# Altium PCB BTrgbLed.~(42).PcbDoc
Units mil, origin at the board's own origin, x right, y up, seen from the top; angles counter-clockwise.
Board outline 3886.28 x 3884.79 mil, 2 copper layers (Top Layer, Bottom Layer); 13 components, 12 nets, 62 pads, 7 vias.
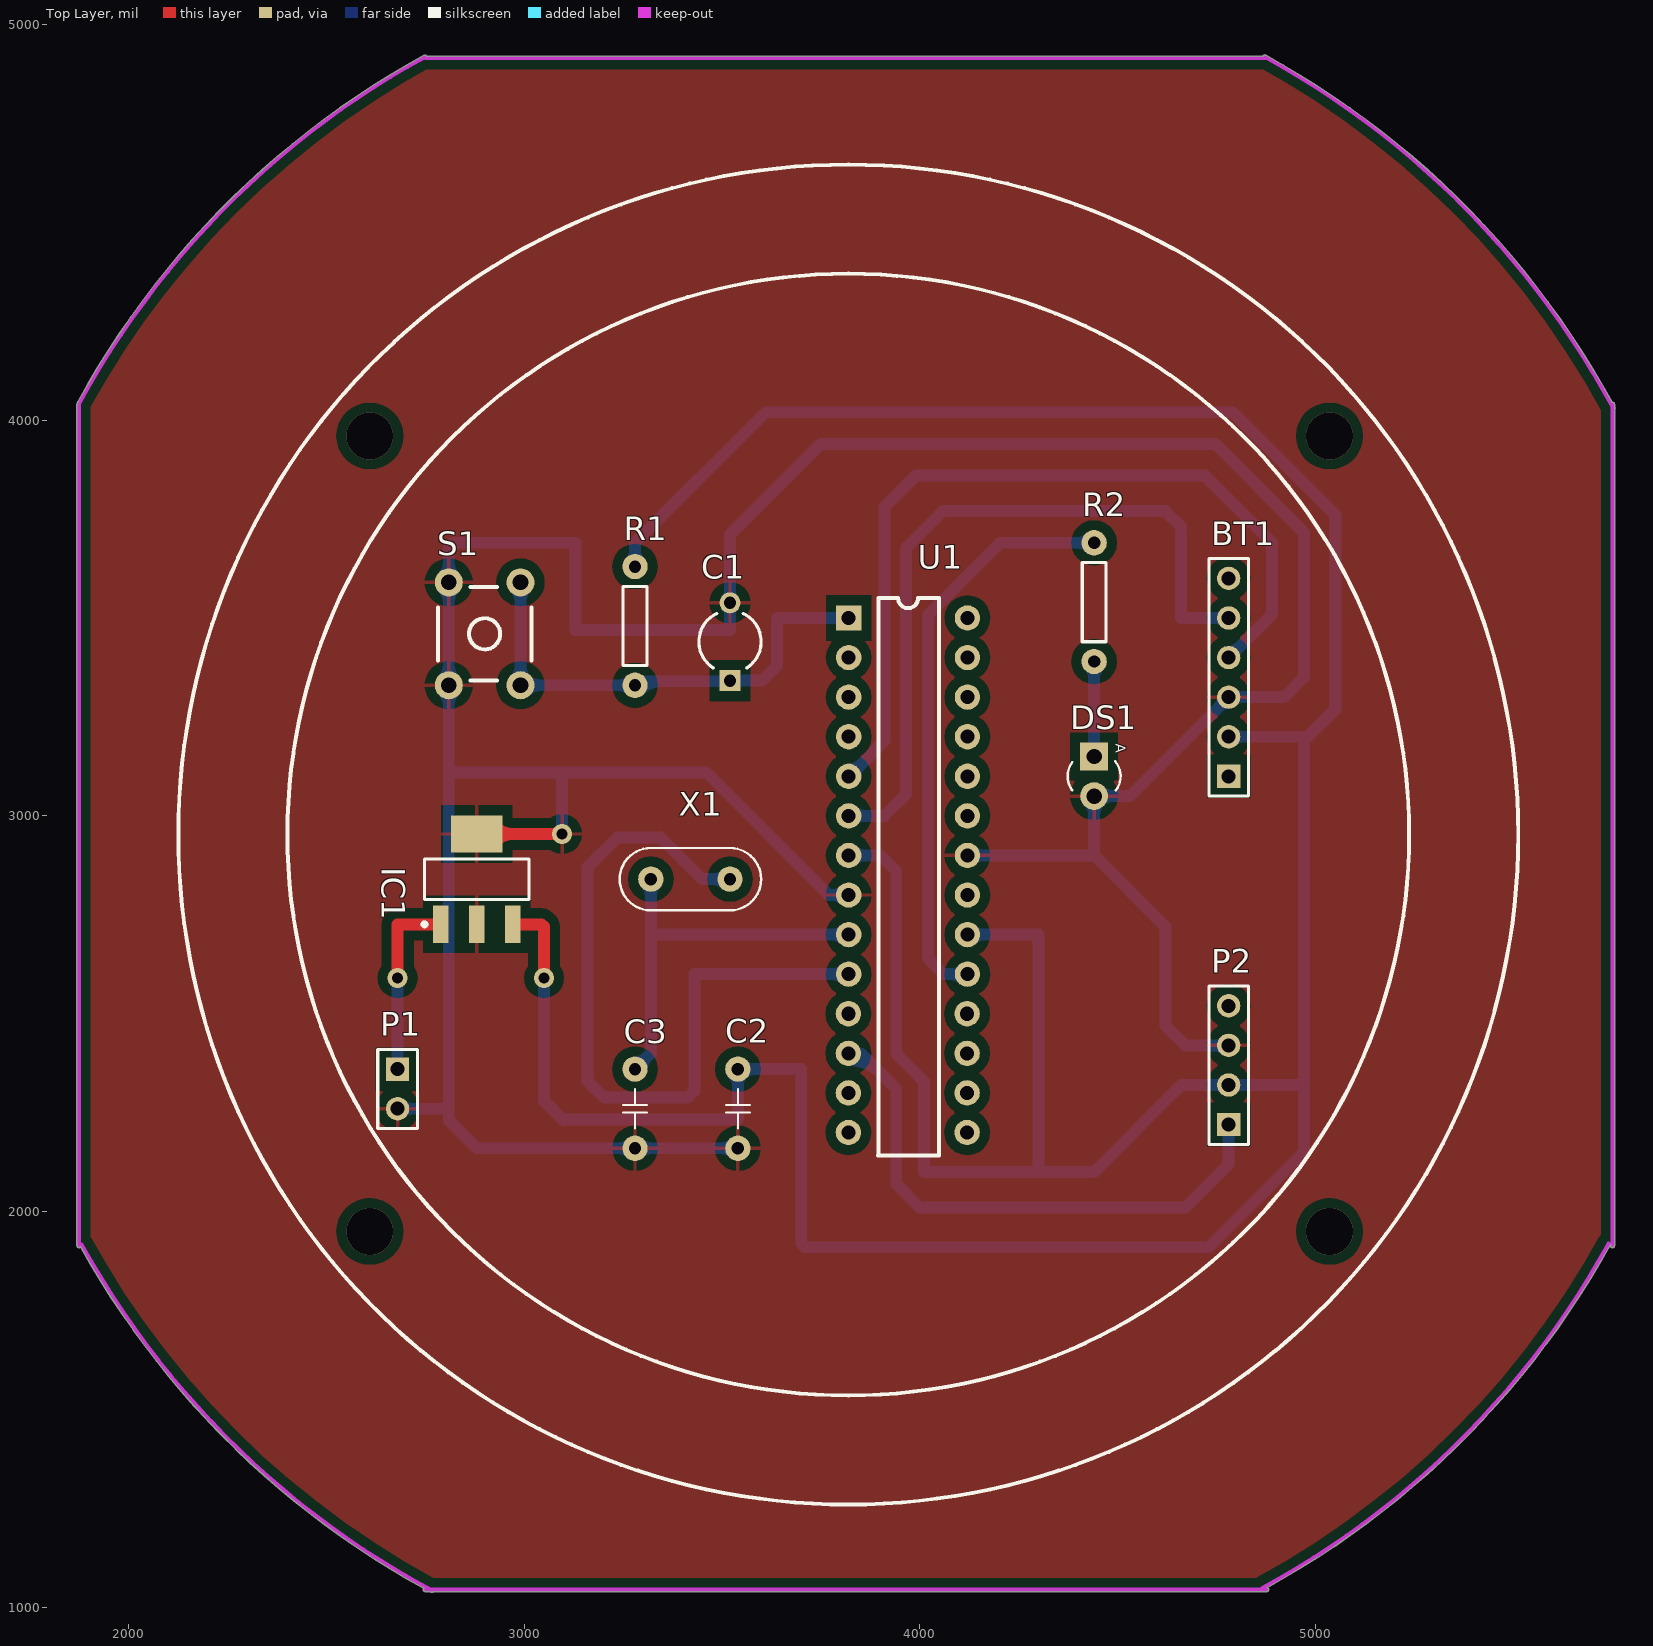
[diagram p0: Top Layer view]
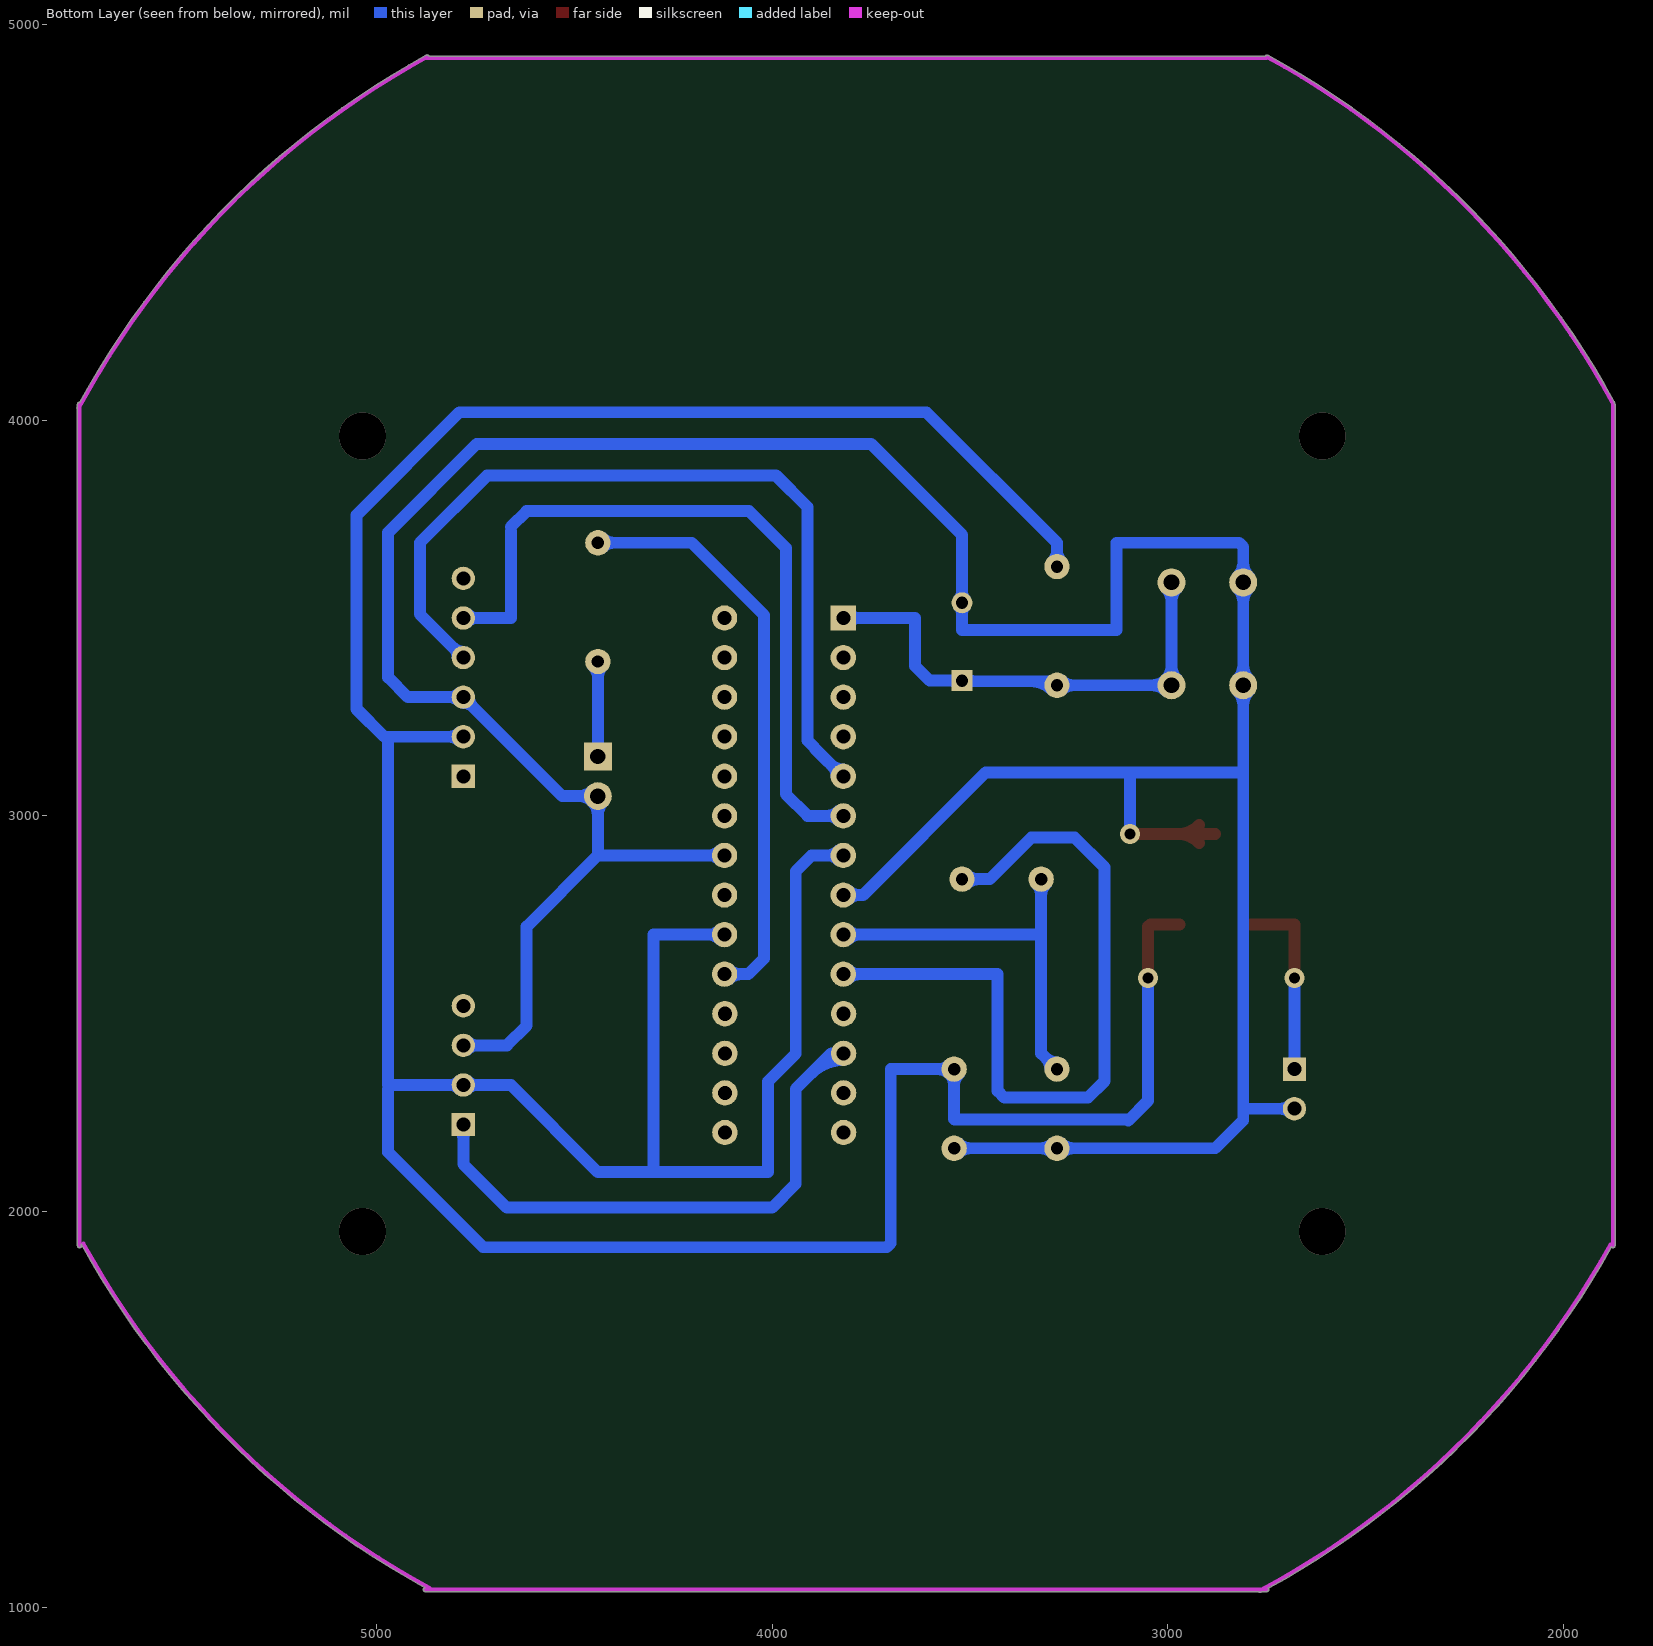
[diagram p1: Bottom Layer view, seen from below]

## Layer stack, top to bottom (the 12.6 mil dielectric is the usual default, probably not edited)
Top Layer: signal copper 1.4
Dielectric: dielectric 12.6, FR-4, Dk 4.8
Bottom Layer: signal copper 1.4

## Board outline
2750,1039.98 2761.53,1039.98 ccw(c3810.28,2985) 2764.5,1038.38 ccw(c2766.88,1042.8) 2771.03,1039.98 4875.98,1039.98 ccw(c4875.98,1045) 4881,1045 ccw(c4875.98,1045) 4877.16,1049.88 ccw(c3810.28,2985) 5744.74,1916.92 ccw(c5740.35,1919.34) 5744.98,1917.43 5744.98,1914.02 ccw(c5750,1914.02) 5755.02,1914.02 5755.02,4027.36 ccw(c5751.25,4030.67) 5756.26,4030.67 ccw(c5751.25,4030.67) 5755.66,4033.05 ccw(c3810.28,2985) 5755.02,4034.26 5755.02,4040 ccw(c5750,4040) 5749.21,4044.95 ccw(c3810.28,2985) 4873.82,4921.96 ccw(c4871.41,4917.56) 4867.03,4920.02 2752.96,4920.02 ccw(c2748.72,4917.33) 2746.3,4921.73 ccw(c3810.28,2985) 1872.41,4046.9 ccw(c1876.81,4044.49) 1871.83,4043.89 ccw(c1875,4040) 1869.98,4040 1869.98,1914.02 ccw(c1875,1914.02) 1879.06,1911.07 ccw(c3810.28,2985) 2746.23,1048.31 ccw(c2750,1045)

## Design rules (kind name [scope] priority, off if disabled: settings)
Clearance 舖銅安全間距 [All] p1: gap=25
Clearance [All] p2: gap=10
PolygonConnect [All] p1: connectstyle=Relief reliefconductorwidth=10 reliefentries=4 polygonreliefangle="90 Angle"
RoutingLayers [All] p1: top layer_v5=FALSE bottom layer_v5=TRUE
RoutingVias [All] p1: holewidth=28 width=50 viastyle="Through Hole" minholewidth=28 minwidth=50 maxholewidth=28 maxwidth=50
SilkscreenOverComponentPads [All] p1: minsilkscreentomaskgap=10
SolderMaskExpansion [All] p1: expansion=4
Width [All] p1: maxlimit=40 minlimit=20 preferedwidth=30
26 further rules are at their usual default settings.

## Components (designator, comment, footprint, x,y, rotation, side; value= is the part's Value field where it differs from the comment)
BT1 "Bluetooth" Bluetooth 4780,3100 r90 top
C1 "47uF" CAPR5-4X5 3520,3440 r90 top
C2 "22pF" C200 3540,2260 r0 top
C3 "22pF" C200 3280,2260 r180 top
DS1 "TX-LED" LED-3mm_G 4440,3100 r270 top
IC1 "AM1117-5V" SOT-223 2880,2840 r90 top
P1 "12V" HDR1X2 2680,2360 r270 top
P2 "環形LED燈" HDR1X4 4780,2220 r90 top
R1 "10k" AXIAL-0.3 3280,3480 r270 top
R2 "220" AXIAL-0.3 4440,3540 r90 top
S1 "SW-PB" TACK6 2900,3460 r90 top
U1 "ATmega328" DIP-28 3820,3500 r270 top
X1 "16MHz" XTAL4-8 3420,2840 r0 top

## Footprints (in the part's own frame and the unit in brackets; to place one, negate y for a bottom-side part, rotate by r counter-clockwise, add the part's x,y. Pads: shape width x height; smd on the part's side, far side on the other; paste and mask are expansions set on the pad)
AXIAL-0.3 [mil] "0.3\" Resistor; 2 Leads"
  round 64 hole 31.5: 1(-150,0) 2(150,0)
  silkscreen extent -100,-30 100,30, body extent -161,-39 165,39, height 86
Bluetooth [mm]
  rect 1.5x1.5 hole 0.9: 1(0,0)
  round 1.5 hole 0.9: 2(2.54,0) 3(5.08,0) 4(7.62,0) 5(10.16,0) 6(12.7,0)
  silkscreen extent -1.27,-1.27 13.97,1.27, body extent -1.25,-1.3 13.97,1.28, height 11
C200 [mil] "塑膠電容器"
  round 64 hole 31.5: 1(0,100) 2(0,-100)
  silkscreen extent -30,-50 30,50, body extent -41,-136 39,135, height 354
CAPR5-4X5 [mm] "Capacitor; 2 Leads"
  rect 1.35x1.35 hole 0.8: 1(-2.5,0)
  round 1.35 hole 0.8: 2(2.5,0)
  silkscreen extent -1.69,-2 1.82,2
DIP-28 [mil]
  rect 64x64 hole 35.43: 1(0,0)
  round 64 hole 35.43: 2(100,0) 3(200,0) 4(300,0) 5(400,0) 6(500,0) 7(600,0) 8(700,0) 9(800,0) 10(900,0) 11(1000,-0.79) 12(1100,-0.79) 13(1200,-0.79) 14(1300,-0.79) 15(1300,299.21) 16(1200,299.21) 17(1100,299.21) 18(1000,299.21) 19(900,300) 20(800,300) 21(700,300) 22(600,300) 23(500,300) 24(400,300) 25(300,300) 26(200,300) 27(100,300) 28(0,300)
  silkscreen extent -50,74 1358,228, body extent -53,-5 1358,304, height 209
HDR1X2 [mm] "Connector; Header; 2 Position"
  rect 1.5x1.5 hole 0.9: 1(0,0)
  round 1.5 hole 0.9: 2(2.54,0)
  silkscreen extent -1.27,-1.27 3.81,1.27
HDR1X4 [mm] "Connector; Header; 4 Position"
  rect 1.5x1.5 hole 0.9: 1(0,0)
  round 1.5 hole 0.9: 2(2.54,0) 3(5.08,0) 4(7.62,0)
  silkscreen extent -1.27,-1.27 8.89,1.27
LED-3mm_G [mil] "3mm LED_Green"
  rect 70x70 hole 39: 1(-50,0)
  round 70 hole 39: 2(50,0)
  silkscreen extent -38,-67 35,67, body extent -66,-68 67,66, height 181
SOT-223 [mm] "SOT223, 4-Leads, Body 6.7x7.3mm (max), Pitch 2.30mm, IPC Medium Density"
  rect 2.4x1 smd: 1(-2.9,2.3) 2(-2.9,0) 3(-2.9,-2.3)
  rect 2.4x3.3 smd: 2(2.9,0)
  silkscreen extent -3.02,-3.35 1.3,3.47, body extent -1.86,-3.35 1.86,3.35, height 1.8
TACK6 [mm]
  round 1.8 hole 1: 1(-3.3,2.3) 1(3.3,2.3) 2(-3.3,-2.3) 2(3.3,-2.3)
  silkscreen extent -3,-3 3,3, body extent -3,-3.01 3.08,3.04, height 8
XTAL4-8 [mil]
  round 64 hole 31.5: 1(-100,0) 2(100,0)
  silkscreen extent -179,-79 179,79, body extent -178,-80 192,79, height 157

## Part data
C1: library part "Cap Pol1", "Polarized Capacitor (Radial)"
C2 C3: library part Cap, "Capacitor"
DS1: library part LED, "Typical INFRARED GaAs LED"
IC1: library part AM1117
P1: library part "Header 2", "Header, 2-Pin"
P2: library part "Header 4", "Header, 4-Pin"
R1 R2: library part Res, "Resistor"
S1: "Switch"
U1: "Arduino"
X1: library part XTAL, "Crystal Oscillator"

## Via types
v1: diameter 118.11, hole 118.11, Top Layer to Bottom Layer, 4 vias
v2: diameter 50, hole 28, Top Layer to Bottom Layer, 3 vias

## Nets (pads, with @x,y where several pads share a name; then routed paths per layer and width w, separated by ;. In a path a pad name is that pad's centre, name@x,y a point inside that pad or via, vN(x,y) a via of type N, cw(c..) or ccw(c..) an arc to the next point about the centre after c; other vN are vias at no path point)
DI: P2.1 U1.12 | length 1699.9
  Bottom Layer w30: U1.12 3850,2400 3940,2310 3940,2070 4000,2010 4670,2010 4780,2120 P2.1 ; 4780,2184.93 cw(c4815.07,2184.93) 4790.27,2209.73 ccw(c4815.07,2184.93) 4780,2184.93 ; 4780,2184.93 ccw(c4744.93,2184.93) 4769.73,2209.73 cw(c4744.93,2184.93) 4780,2184.93 ; U1.12@3819.21,2383 cw(c3819.21,2267.63) 3900.79,2349.21 ccw(c3819.21,2267.63) U1.12@3819.21,2383
DO: P2.4
GND: BT1.3 C1.2 C2.2 C3.1 DS1.2 IC1.2 P1.2 P2.3 S1.1 U1.8 U1.22 | length 11241.6
  Top Layer w30: IC1.2@2880,2954.17 v2(3095.83,2954.17) ; 2975.56,2954.17 cw(c2975.56,3032.02) 2920.52,2976.97 ccw(c2975.56,3032.02) 2975.56,2954.17 ; 2975.56,2954.17 ccw(c2975.56,2876.33) 2920.52,2931.37 cw(c2975.56,2876.33) 2975.56,2954.17
  Bottom Layer w30: P1.2 2804.45,2260 ; S1.1@2809.45,3580.49 2809.45,3330.08 2809.45,2230.55 2880,2160 C3.1 C2.2 ; S1.1@2809.45,3589.92 2809.45,3679.45 2820,3690 3130,3690 3130,3470 3520,3470 C1.2 3520,3710 3750,3940 4746,3940 4970,3716 4970,3350 4920,3300 BT1.3 4530,3050 DS1.2 4440,2900 ; 2819.45,3110 3095.83,3110 ; v2(3095.83,2954.17) 3095.83,3110 ; U1.8 3770,2800 3460,3110 3095.83,3110 ; U1.22 4440,2900 ; P2.3 4670,2420 4620,2470 4620,2720 4440,2900 ; 2715.07,2260 cw(c2715.07,2295.07) 2690.27,2270.27 ccw(c2715.07,2295.07) 2715.07,2260 ; 2715.07,2260 ccw(c2715.07,2224.93) 2690.27,2249.73 cw(c2715.07,2224.93) 2715.07,2260 ; 2809.45,3280.75 cw(c2858.78,3280.75) 2823.9,3315.63 ccw(c2858.78,3280.75) 2809.45,3280.75 ; 2809.45,3280.75 ccw(c2760.12,3280.75) 2795,3315.63 cw(c2760.12,3280.75) 2809.45,3280.75 ; 2809.45,3379.41 cw(c2760.12,3379.41) 2795,3344.53 ccw(c2760.12,3379.41) 2809.45,3379.41 ; 2809.45,3379.41 ccw(c2858.78,3379.41) 2823.9,3344.53 cw(c2858.78,3379.41) 2809.45,3379.41 ; 2809.45,3540.59 cw(c2858.78,3540.59) 2823.9,3575.47 ccw(c2858.78,3540.59) 2809.45,3540.59 ; 2809.45,3540.59 ccw(c2760.12,3540.59) 2795,3575.47 cw(c2760.12,3540.59) 2809.45,3540.59 ; 2809.45,3639.25 cw(c2760.12,3639.25) 2795,3604.37 ccw(c2760.12,3639.25) 2809.45,3639.25 ; 2809.45,3639.25 ccw(c2858.78,3639.25) 2823.9,3604.37 cw(c2858.78,3639.25) 2809.45,3639.25 ; 3238.96,2160 cw(c3238.96,2118.96) 3267.98,2147.98 ccw(c3238.96,2118.96) 3238.96,2160 ; 3238.96,2160 ccw(c3238.96,2201.04) 3267.98,2172.02 cw(c3238.96,2201.04) 3238.96,2160 ; 3321.04,2160 cw(c3321.04,2201.04) 3292.02,2172.02 ccw(c3321.04,2201.04) 3321.04,2160 ; 3321.04,2160 ccw(c3321.04,2118.96) 3292.02,2147.98 cw(c3321.04,2118.96) 3321.04,2160 ; 3498.96,2160 cw(c3498.96,2118.96) 3527.98,2147.98 ccw(c3498.96,2118.96) 3498.96,2160 ; 3498.96,2160 ccw(c3498.96,2201.04) 3527.98,2172.02 cw(c3498.96,2201.04) 3498.96,2160 ; 3520,3510.48 cw(c3547.94,3510.48) 3528.18,3530.24 ccw(c3547.94,3510.48) 3520,3510.48 ; 3520,3510.48 ccw(c3492.06,3510.48) 3511.82,3530.24 cw(c3492.06,3510.48) 3520,3510.48 ; 3520,3566.37 cw(c3492.06,3566.37) 3511.82,3546.61 ccw(c3492.06,3566.37) 3520,3566.37 ; 3520,3566.37 ccw(c3547.94,3566.37) 3528.18,3546.61 cw(c3547.94,3566.37) 3520,3566.37 ; 3778.96,2800 cw(c3778.96,2758.96) 3807.98,2787.98 ccw(c3778.96,2758.96) 3778.96,2800 ; 3778.96,2800 ccw(c3778.96,2841.04) 3807.98,2812.02 cw(c3778.96,2841.04) 3778.96,2800 ; 4161.04,2900 cw(c4161.04,2941.04) 4132.02,2912.02 ccw(c4161.04,2941.04) 4161.04,2900 ; 4161.04,2900 ccw(c4161.04,2858.96) 4132.02,2887.98 cw(c4161.04,2858.96) 4161.04,2900 ; 4440,3001.72 cw(c4488.28,3001.72) DS1.2@4454.14,3035.86 ; 4440,3001.72 ccw(c4391.72,3001.72) 4425.86,3035.86 cw(c4391.72,3001.72) 4440,3001.72 ; 4440,3001.72 cw(c4488.28,3001.72) DS1.2@4454.14,3035.86 ; DS1.2@4454.14,3035.86 cw(c4488.28,3001.72) 4488.28,3050 ; DS1.2@4454.14,3035.86 cw(c4488.28,3001.72) 4488.28,3050 ; 4488.28,3050 cw(c4488.28,3098.28) 4454.14,3064.14 ccw(c4488.28,3098.28) 4488.28,3050 ; 4744.93,2420 cw(c4744.93,2384.93) 4769.73,2409.73 ccw(c4744.93,2384.93) 4744.93,2420 ; 4744.93,2420 ccw(c4744.93,2455.07) 4769.73,2430.27 cw(c4744.93,2455.07) 4744.93,2420 ; 4755.2,3275.2 cw(c4780,3250.4) 4780,3285.47 ccw(c4780,3250.4) 4755.2,3275.2 ; 4755.2,3275.2 ccw(c4730.4,3300) 4765.47,3300 cw(c4730.4,3300) 4755.2,3275.2 ; 4815.07,3300 cw(c4815.07,3335.07) 4790.27,3310.27 ccw(c4815.07,3335.07) 4815.07,3300 ; 4815.07,3300 ccw(c4815.07,3264.93) 4790.27,3289.73 cw(c4815.07,3264.93) 4815.07,3300
NetC1_1: C1.1 R1.2 S1.2 U1.1 | length 2195.5
  Bottom Layer w30: S1.2@2990.55,3320.65 S1.2@2990.55,3330.08 ; S1.2@2990.55,3580.49 S1.2@2990.55,3330.08 ; R1.2@3279.92,3330.08 S1.2@2990.55,3330.08 ; R1.2@3280,3340 C1.1@3508.43,3340 ; C1.1 3601.57,3341.57 3638.43,3378.43 3638.43,3500 U1.1 ; 2990.55,3379.41 cw(c2941.22,3379.41) 2976.1,3344.53 ccw(c2941.22,3379.41) 2990.55,3379.41 ; 2990.55,3379.41 ccw(c3039.88,3379.41) S1.2@3005,3344.53 ; 2990.55,3379.41 ccw(c3039.88,3379.41) S1.2@3005,3344.53 ; 2990.55,3540.59 cw(c3039.88,3540.59) 3005,3575.47 ccw(c3039.88,3540.59) 2990.55,3540.59 ; 2990.55,3540.59 ccw(c2941.22,3540.59) 2976.1,3575.47 cw(c2941.22,3540.59) 2990.55,3540.59 ; S1.2@3005,3344.53 ccw(c3039.88,3379.41) 3039.88,3330.08 ; S1.2@3005,3344.53 ccw(c3039.88,3379.41) 3039.88,3330.08 ; 3039.88,3330.08 ccw(c3039.88,3280.75) 3005,3315.63 cw(c3039.88,3280.75) 3039.88,3330.08 ; 3547.94,3341.57 cw(c3547.94,3369.52) 3528.18,3349.76 ccw(c3547.94,3369.52) 3547.94,3341.57 ; 3547.94,3341.57 ccw(c3547.94,3313.63) 3528.18,3333.39 cw(c3547.94,3313.63) 3547.94,3341.57 ; 3778.96,3500 cw(c3778.96,3458.96) 3807.98,3487.98 ccw(c3778.96,3458.96) 3778.96,3500 ; 3778.96,3500 ccw(c3778.96,3541.04) 3807.98,3512.02 cw(c3778.96,3541.04) 3778.96,3500 ; 3238.77,3330.08 cw(c3238.77,3288.77) 3267.98,3317.98 ccw(c3238.77,3288.77) 3238.77,3330.08 ; 3239.15,3330.08 ccw(c3239.15,3370.85) 3267.98,3342.02 cw(c3239.15,3370.85) 3239.15,3330.08 ; R1.2@3292.02,3317.98 cw(c3345.18,3264.82) 3345.18,3340 ccw(c3345.18,3264.82) R1.2@3292.02,3317.98 ; 3488.26,3340 ccw(c3488.26,3373.32) 3511.82,3349.76 cw(c3488.26,3373.32) 3488.26,3340
NetC2_2: U1.10 X1.2 | length 2211.9
  Bottom Layer w30: X1.2 3450,2840 3345,2945 3235,2945 3160,2870 3160,2330 3202,2288 3413,2288 3430,2305 3430,2600 U1.10 ; 3478.96,2840 cw(c3478.96,2798.96) 3507.98,2827.98 ccw(c3478.96,2798.96) 3478.96,2840 ; 3478.96,2840 ccw(c3478.96,2881.04) 3507.98,2852.02 cw(c3478.96,2881.04) 3478.96,2840 ; 3778.96,2600 cw(c3778.96,2558.96) 3807.98,2587.98 ccw(c3778.96,2558.96) 3778.96,2600 ; 3778.96,2600 ccw(c3778.96,2641.04) 3807.98,2612.02 cw(c3778.96,2641.04) 3778.96,2600
NetC3_2: C3.2 U1.9 X1.1 | length 1378.4
  Bottom Layer w30: C3.2 3320,2400 X1.1 ; 3325,2700 U1.9 ; 3309.02,2389.02 cw(c3280,2418.04) 3280,2377 ccw(c3280,2418.04) 3309.02,2389.02 ; 3309.02,2389.02 ccw(c3338.04,2360) 3297,2360 cw(c3338.04,2360) 3309.02,2389.02 ; 3320,2798.96 cw(c3361.04,2798.96) 3332.02,2827.98 ccw(c3361.04,2798.96) 3320,2798.96 ; 3320,2798.96 ccw(c3278.96,2798.96) 3307.98,2827.98 cw(c3278.96,2798.96) 3320,2798.96 ; 3778.96,2700 cw(c3778.96,2658.96) 3807.98,2687.98 ccw(c3778.96,2658.96) 3778.96,2700 ; 3778.96,2700 ccw(c3778.96,2741.04) 3807.98,2712.02 cw(c3778.96,2741.04) 3778.96,2700
NetDS1_1: DS1.1 R2.1 | length 368.9
  Bottom Layer w30: DS1.1 R2.1 ; 4440,3348.96 cw(c4481.04,3348.96) 4452.02,3377.98 ccw(c4481.04,3348.96) 4440,3348.96 ; 4440,3348.96 ccw(c4398.96,3348.96) 4427.98,3377.98 cw(c4398.96,3348.96) 4440,3348.96
NetIC1_1: IC1.1 P1.1 | length 579.6
  Top Layer w30: v2(2680,2590) 2680,2720 ; 2680,2725.83 IC1.1
  Bottom Layer w30: P1.1 v2(2680,2590) ; 2680,2395.07 cw(c2644.93,2395.07) 2669.73,2370.27 ccw(c2644.93,2395.07) 2680,2395.07 ; 2680,2395.07 ccw(c2715.07,2395.07) 2690.27,2370.27 cw(c2715.07,2395.07) 2680,2395.07
NetR2_2: R2.2 U1.19 | length 1737.2
  Bottom Layer w30: U1.19 4060,2600 4020,2640 4020,3507 4203,3690 R2.2 ; 4078.96,2600 cw(c4078.96,2558.96) 4107.98,2587.98 ccw(c4078.96,2558.96) 4078.96,2600 ; 4078.96,2600 ccw(c4078.96,2641.04) 4107.98,2612.02 cw(c4078.96,2641.04) 4078.96,2600 ; 4398.96,3690 cw(c4398.96,3648.96) 4427.98,3677.98 ccw(c4398.96,3648.96) 4398.96,3690 ; 4398.96,3690 ccw(c4398.96,3731.04) 4427.98,3702.02 cw(c4398.96,3731.04) 4398.96,3690
RX: BT1.5 U1.6 | length 2245.8
  Bottom Layer w30: U1.6@3821.82,3000 U1.6 3910,3000 3965,3055 3965,3130 ; 3965,3255 3965,3130 ; 4660,3720 4660,3500 BT1.5 ; 4660,3730 4620,3770 4058,3770 3965,3677 3965,3130 ; 3861.04,3000 cw(c3861.04,3041.04) 3832.02,3012.02 ccw(c3861.04,3041.04) 3861.04,3000 ; 3861.04,3000 ccw(c3861.04,2958.96) 3832.02,2987.98 cw(c3861.04,2958.96) 3861.04,3000 ; 4744.93,3500 cw(c4744.93,3464.93) 4769.73,3489.73 ccw(c4744.93,3464.93) 4744.93,3500 ; 4744.93,3500 ccw(c4744.93,3535.07) 4769.73,3510.27 cw(c4744.93,3535.07) 4744.93,3500
TX: BT1.4 U1.5 | length 2376.6
  Bottom Layer w30: U1.5 3821.82,3100 3892,3170.18 3892,3172 3910,3190 3910,3780 3990,3860 4720,3860 4890,3690 4890,3510 BT1.4 ; 4804.8,3424.8 cw(c4780,3449.6) 4780,3414.53 ccw(c4780,3449.6) 4804.8,3424.8 ; 4804.8,3424.8 ccw(c4829.6,3400) 4794.53,3400 cw(c4829.6,3400) 4804.8,3424.8 ; U1.5@3820,3117 ccw(c3820,3162.44) 3852.13,3130.31 cw(c3820,3162.44) U1.5@3820,3117 ; U1.5@3837,3100 cw(c3873.64,3100) 3847.73,3125.91 ccw(c3873.64,3100) U1.5@3837,3100
VCC: BT1.2 C2.1 IC1.3 P2.2 R1.1 U1.7 U1.20 | length 10750.8
  Top Layer w30: IC1.3 3044.17,2725.83 ; v2(3050,2590) 3050,2720
  Bottom Layer w30: v2(3050,2590) 3050,2280 3100,2230 3103,2233 3539,2233 3540,2234 C2.1 3700,2360 3700,1920 3710,1910 4730,1910 4970,2150 4970,2310 ; R1.1 3280,3690 3610,4020 4790,4020 5050,3760 5050,3270 4980,3200 BT1.2 ; U1.7 3900,2900 3940,2860 3940,2399 4010,2329 4010,2100 4300,2100 ; U1.20 4300,2700 4300,2100 ; 4970,3190 4970,2320 P2.2 4660,2320 4440,2100 4300,2100 ; 3280,3671.04 cw(c3238.96,3671.04) 3267.98,3642.02 ccw(c3238.96,3671.04) 3280,3671.04 ; 3280,3671.04 ccw(c3321.04,3671.04) 3292.02,3642.02 cw(c3321.04,3671.04) 3280,3671.04 ; 3540,2318.96 cw(c3581.04,2318.96) C2.1@3552.02,2347.98 ; 3540,2318.96 ccw(c3498.96,2318.96) 3527.98,2347.98 cw(c3498.96,2318.96) 3540,2318.96 ; 3540,2318.96 cw(c3581.04,2318.96) C2.1@3552.02,2347.98 ; C2.1@3552.02,2347.98 cw(c3581.04,2318.96) 3581.04,2360 ; C2.1@3552.02,2347.98 cw(c3581.04,2318.96) 3581.04,2360 ; 3581.04,2360 cw(c3581.04,2401.04) 3552.02,2372.02 ccw(c3581.04,2401.04) 3581.04,2360 ; 3861.04,2900 cw(c3861.04,2941.04) 3832.02,2912.02 ccw(c3861.04,2941.04) 3861.04,2900 ; 3861.04,2900 ccw(c3861.04,2858.96) 3832.02,2887.98 cw(c3861.04,2858.96) 3861.04,2900 ; 4161.04,2700 cw(c4161.04,2741.04) 4132.02,2712.02 ccw(c4161.04,2741.04) 4161.04,2700 ; 4161.04,2700 ccw(c4161.04,2658.96) 4132.02,2687.98 cw(c4161.04,2658.96) 4161.04,2700 ; 4744.93,2320 cw(c4744.93,2284.93) 4769.73,2309.73 ccw(c4744.93,2284.93) 4744.93,2320 ; 4744.93,2320 ccw(c4744.93,2355.07) 4769.73,2330.27 cw(c4744.93,2355.07) 4744.93,2320 ; 4815.07,2320 cw(c4815.07,2355.07) 4790.27,2330.27 ccw(c4815.07,2355.07) 4815.07,2320 ; 4815.07,2320 ccw(c4815.07,2284.93) 4790.27,2309.73 cw(c4815.07,2284.93) 4815.07,2320 ; 4815.07,3200 cw(c4815.07,3235.07) 4790.27,3210.27 ccw(c4815.07,3235.07) 4815.07,3200 ; 4815.07,3200 ccw(c4815.07,3164.93) 4790.27,3189.73 cw(c4815.07,3164.93) 4815.07,3200
pads on no net: BT1.1 BT1.6 U1.2 U1.3 U1.4 U1.11 U1.13 U1.14 U1.15 U1.16 U1.17 U1.18 U1.21 U1.23 U1.24 U1.25 U1.26 U1.27 U1.28
copper on no net:
  other v1: 2610,1950 5035,1950 2610,3960 5035,3960

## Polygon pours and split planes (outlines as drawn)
GND on Top Layer "Top Layer-No Net" (solid): 1873.98,1914.02 1875.81,1913.41 1875.82,1913.42 1882.55,1913.01 ccw(c3810.28,2985) 2748.16,1051.82 2750.17,1049 4873.26,1049 4875.23,1053.38 ccw(c3810.28,2985) 5741.24,1918.85 5741.24,1918.86 5741.29,1918.96 5748.98,1917.43 5748.98,1914.02 5751.02,1914.02 5751.02,4027.36 5752.01,4030 5752.02,4030.01 5752.26,4030.67 5752.14,4031.15 5751.49,4032.36 5751.02,4034.26 5751.02,4040 5749.85,4041 5749.84,4041 5745.7,4043.03 ccw(c3810.28,2985) 4871.9,4918.45 4871.89,4918.46 4870.52,4918.06 4867.03,4916.02 2752.96,4916.02 2749.58,4917.88 2749.57,4917.89 2748.23,4918.22 ccw(c3810.28,2985) 1875.92,4044.98 1875.91,4044.97 1875.8,4044.38 1875.8,4044.37 1875.83,4043.89 1874.36,4040.79 1874.35,4040.78 1873.98,4040

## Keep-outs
Keep-Out Layer:
  lines w10: 1875,1914.02 1875,4040 ; 1876.81,4044.49 cw(c3810.28,2985) 2748.72,4917.33 ; 1881.24,1917.47 ccw(c3810.28,2985) 2766.88,1042.8 ; 2750,1045 4875.98,1045 ; 2750,4915 4875.98,4915 ; 4865.51,1049.21 ccw(c3810.28,2985) 5740.35,1919.34 ; 4871.41,4917.56 cw(c3810.28,2985) 5751.25,4030.67 ; 5750,1914.02 5750,4040

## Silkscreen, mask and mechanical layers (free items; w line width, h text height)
Top Overlay:
  circle w10: c3818.9,2952.76 r1417.32
  circle w10: c3818.9,2952.76 r1692.91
